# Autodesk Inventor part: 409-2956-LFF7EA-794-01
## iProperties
Created: 2010-09
Part Number: 409-2956-LFF7EA-794-01
Material: 3/4" LIGUID TIGHT
Document SubType Name: Modeling
Designer: S. Boerckel
Engineer: Steve Boerckel
Mass: 113.184 g
Surface Area: 476.907 cm^2
Volume: 80.8454 cm^3
Density: 1.4 g/cm^3
Description: LIQUID TIGHT
Length: 12.091 in
Author: S. Boerckel
Revision Number: 0
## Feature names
1. Sweep1
2. Extrusion1
